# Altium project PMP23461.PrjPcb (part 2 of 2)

## Sheet PMP23461 CLLLC Sensing.SchDoc
size 431 x 279 mm; Date: Not shown in title block; ApprovedBy: Not shown in title block; CheckedBy: Not shown in title block; Author: Not shown in title block; CompanyName: Not shown in title block; Engineer: Not shown in title block; Organization: Not shown in title block; Address1: Not shown in title block; Address2: Not shown in title block; Address3: Not shown in title block; Address4: Not shown in title block; DocumentNumber: 2; Revision: Use project parameter SCH_Rev; SheetNumber: 2; SheetTotal: 2; PageSetup: Record=PageOptions¦CenterHorizontal=True¦CenterVertical=True¦PrintScale=1.00¦XCorrection=1.00¦YCorrection=1.00¦PrintKind=0¦BorderSize=5000000¦LeftOffset=0¦BottomOffset=0¦Orientation=2¦PaperLength=1000¦PaperWidth=1000¦Scale=100¦PaperSource=15¦PrintQuality=600¦MediaType=1¦DitherType=10¦PaperKind=Letter¦PrintScaleMode=1
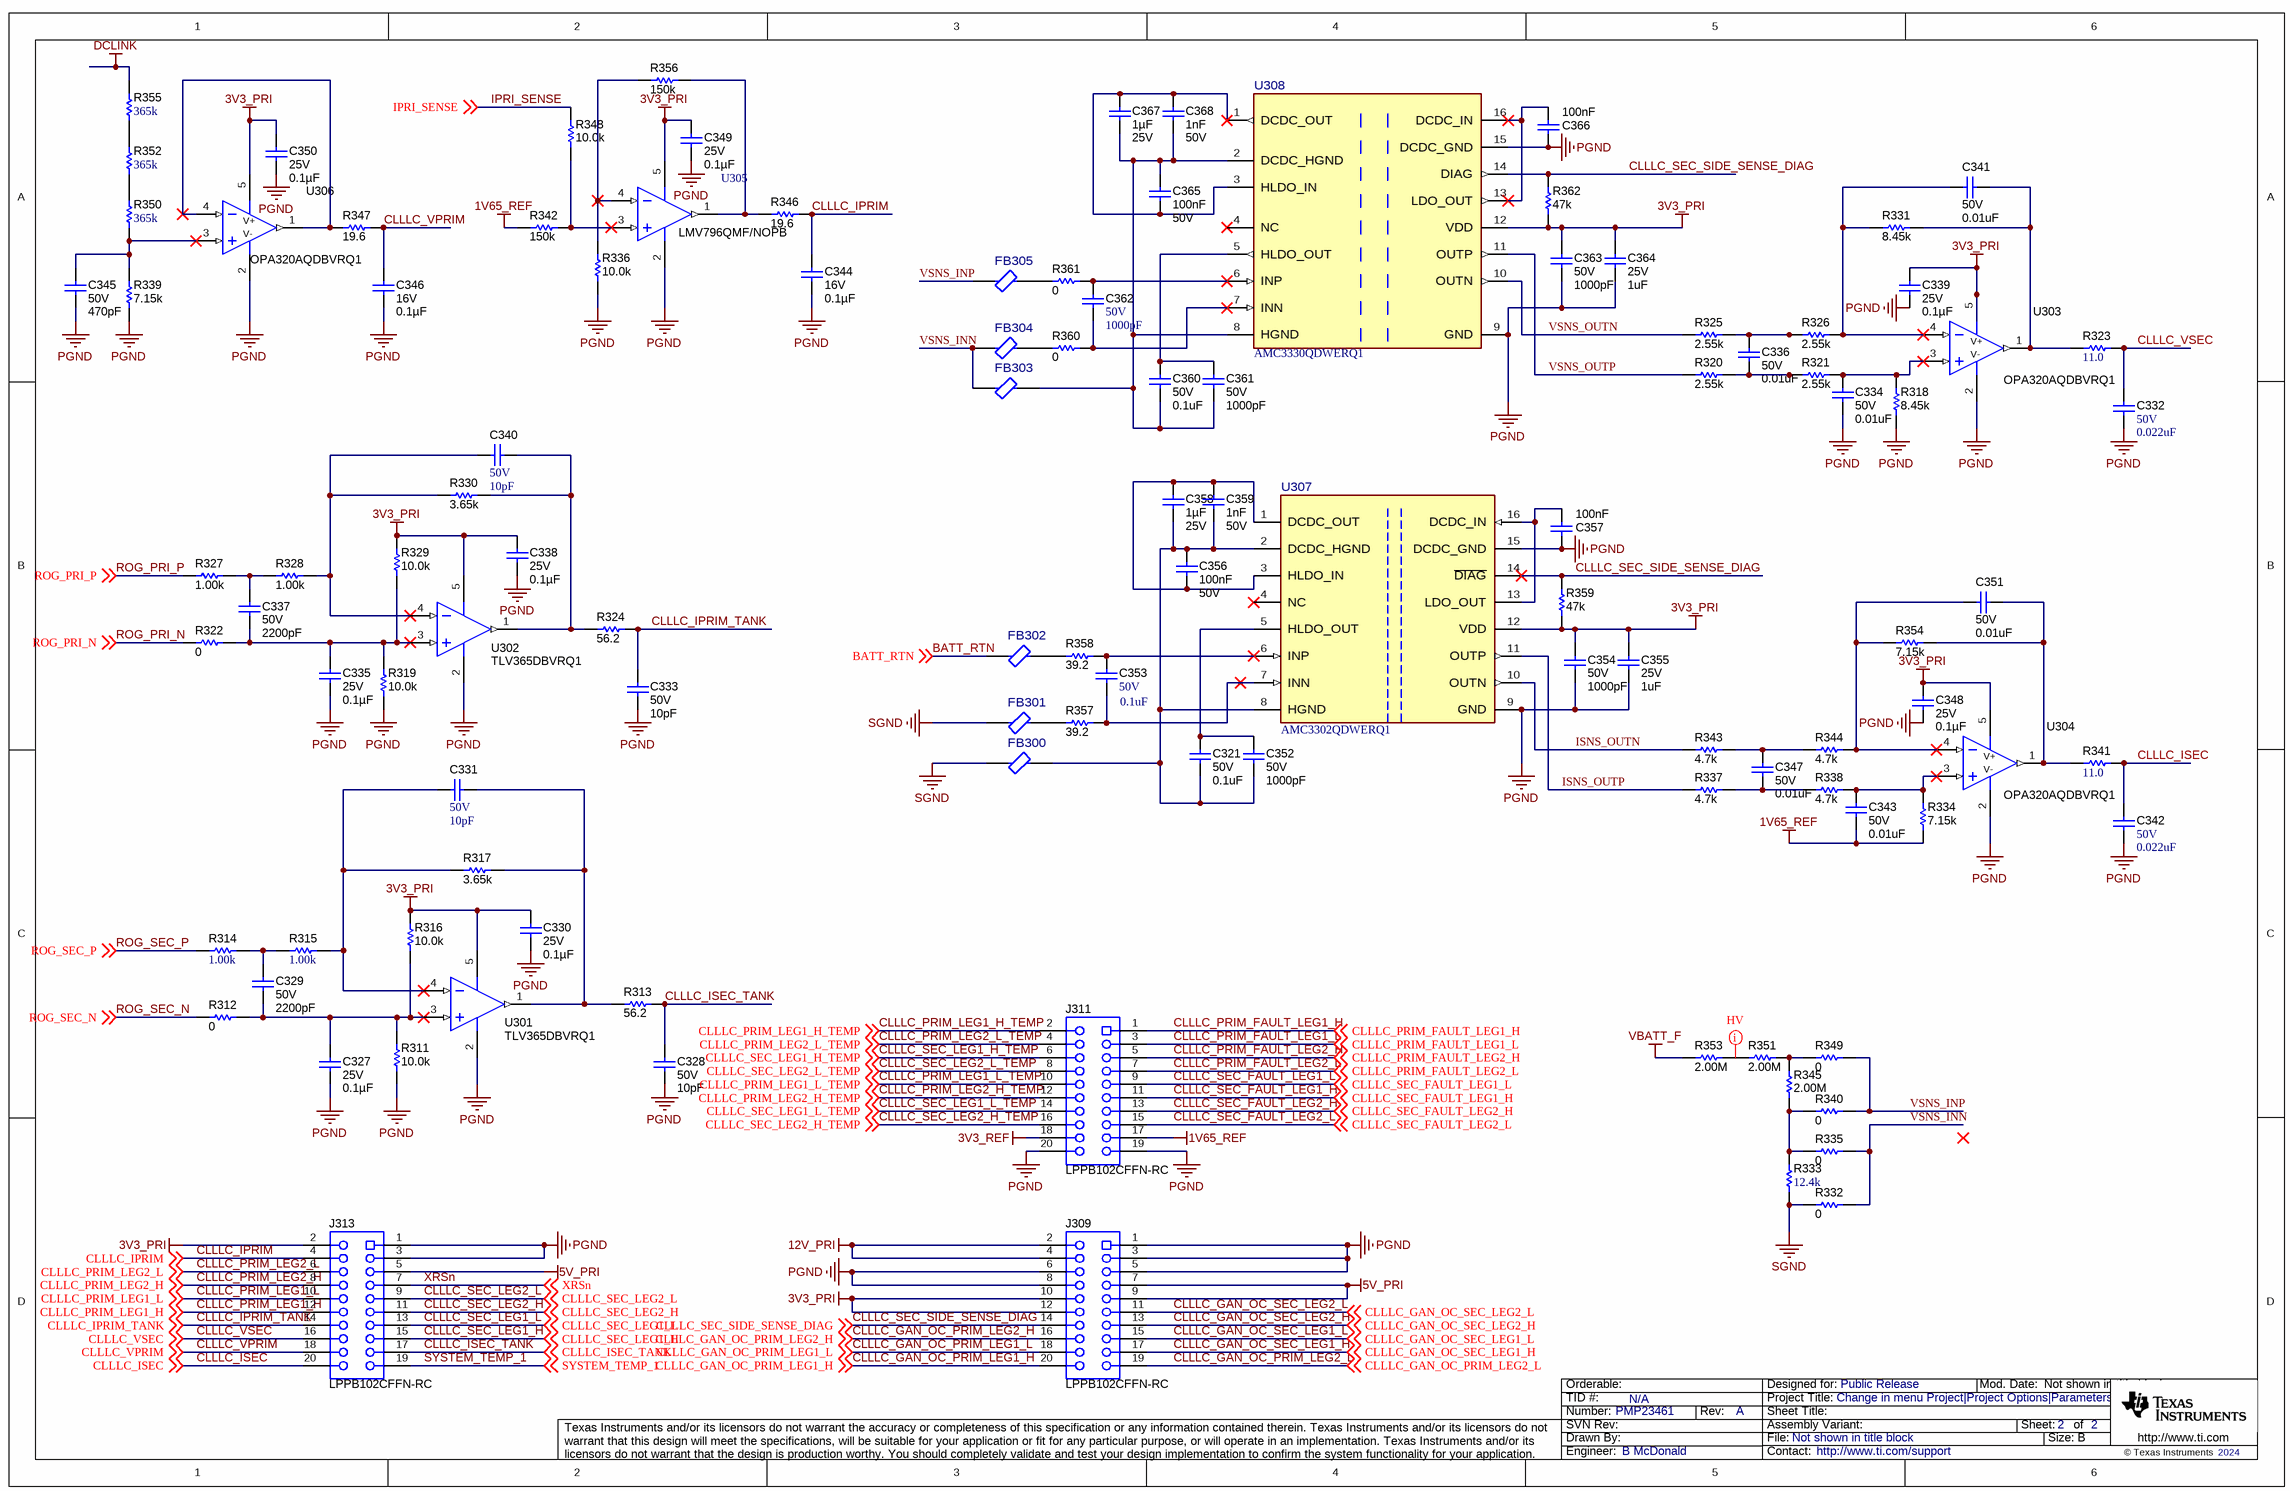
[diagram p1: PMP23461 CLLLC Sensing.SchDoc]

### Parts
C321  VDC_V: 50V  ValueDisplayed: 0.1uF  [1206_190]  (hidden comment: C3216NP01H104J160AA)
C327  VDC_V: 25V  ValueDisplayed: 0.1µF  [0402]  (hidden comment: CS0402KRX7R8BB104)
C328  VDC_V: 50V  ValueDisplayed: 10pF  [0402]  (hidden comment: 04025U100CAT2A)
C329  VDC_V: 50V  ValueDisplayed: 2200pF  [0402]  (hidden comment: C1005X7R1H222K050BE)
C330  VDC_V: 25V  ValueDisplayed: 0.1µF  [0402]  (hidden comment: CGA2B3X7R1E104K050BB)
C331  VDC_V: 50V  ValueDisplayed: 10pF  [0402]  (hidden comment: 04025U100CAT2A)
C332  VDC_V: 50V  ValueDisplayed: 0.022uF  [0402]  (hidden comment: CGA2B3X7R1H223K050BB)
C333  VDC_V: 50V  ValueDisplayed: 10pF  [0402]  (hidden comment: 04025U100CAT2A)
C334  VDC_V: 50V  ValueDisplayed: 0.01uF  [0402]  (hidden comment: CGA2B3X7R1H103K050BB)
C335  VDC_V: 25V  ValueDisplayed: 0.1µF  [0402]  (hidden comment: CGA2B3X7R1E104K050BB)
C336  VDC_V: 50V  ValueDisplayed: 0.01uF  [0402]  (hidden comment: CGA2B3X7R1H103K050BB)
C337  VDC_V: 50V  ValueDisplayed: 2200pF  [0402]  (hidden comment: CGA2B2X7R1H222K050BA)
C338  VDC_V: 25V  ValueDisplayed: 0.1µF  [0402]  (hidden comment: CGA2B3X7R1E104K050BB)
C339  VDC_V: 25V  ValueDisplayed: 0.1µF  [0402]  (hidden comment: CGA2B3X7R1E104K050BB)
C340  VDC_V: 50V  ValueDisplayed: 10pF  [0402]  (hidden comment: 04025U100CAT2A)
C341  VDC_V: 50V  ValueDisplayed: 0.01uF  [0402]  (hidden comment: CGA2B3X7R1H103K050BB)
C342  VDC_V: 50V  ValueDisplayed: 0.022uF  [0402]  (hidden comment: CGA2B3X7R1H223K050BB)
C343  VDC_V: 50V  ValueDisplayed: 0.01uF  [0402]  (hidden comment: CGA2B3X7R1H103K050BB)
C344  VDC_V: 16V  ValueDisplayed: 0.1µF  [0402]  (hidden comment: GCM155R71C104JA55D)
C345  VDC_V: 50V  ValueDisplayed: 470pF  [0402]  (hidden comment: GCM155R71H471KA37D)
C346  VDC_V: 16V  ValueDisplayed: 0.1µF  [0402]  (hidden comment: GCM155R71C104JA55D)
C347  VDC_V: 50V  ValueDisplayed: 0.01uF  [0402]  (hidden comment: CGA2B3X7R1H103K050BB)
C348  VDC_V: 25V  ValueDisplayed: 0.1µF  [0402]  (hidden comment: CGA2B3X7R1E104K050BB)
C349  VDC_V: 25V  ValueDisplayed: 0.1µF  [0402]  (hidden comment: CGA2B3X7R1E104K050BB)
C350  VDC_V: 25V  ValueDisplayed: 0.1µF  [0402]  (hidden comment: CGA2B3X7R1E104K050BB)
C351  VDC_V: 50V  ValueDisplayed: 0.01uF  [0402]  (hidden comment: CGA2B3X7R1H103K050BB)
C352  VDC_V: 50V  ValueDisplayed: 1000pF  [1206]  (hidden comment: 12065C102KAT2A)
C353  value 0.1uF  VDC_V: 50V  [0402]  (hidden comment: CGA2B3X7R1H104K050BB)
C354  VDC_V: 50V  ValueDisplayed: 1000pF  [1206]  (hidden comment: 12065C102KAT2A)
C355  VDC_V: 25V  ValueDisplayed: 1uF  [1206]  (hidden comment: 12063C105KAT2A)
C356  Cap_F: 100nF  VDC_V: 50V  [0603]  (hidden comment: C0603C104K5RACAUTO)
C357  Cap_F: 100nF  [0603]  (hidden comment: C0603C104K5RACAUTO)
C358  Cap_F: 1µF  VDC_V: 25V  [0603S]  (hidden comment: CGA3E1X7R1E105K080AC)
C359  Cap_F: 1nF  VDC_V: 50V  [0603]  (hidden comment: C0603C102K5RACTU)
C360  VDC_V: 50V  ValueDisplayed: 0.1uF  [1206_190]  (hidden comment: C3216NP01H104J160AA)
C361  VDC_V: 50V  ValueDisplayed: 1000pF  [1206]  (hidden comment: 12065C102KAT2A)
C362  VDC_V: 50V  ValueDisplayed: 1000pF  [0402]  (hidden comment: CGA2B2X7R1H102K050BA)
C363  VDC_V: 50V  ValueDisplayed: 1000pF  [1206]  (hidden comment: 12065C102KAT2A)
C364  VDC_V: 25V  ValueDisplayed: 1uF  [1206]  (hidden comment: 12063C105KAT2A)
C365  Cap_F: 100nF  VDC_V: 50V  [0603]  (hidden comment: C0603C104K5RACAUTO)
C366  Cap_F: 100nF  [0603]  (hidden comment: C0603C104K5RACAUTO)
C367  Cap_F: 1µF  VDC_V: 25V  [0603S]  (hidden comment: CGA3E1X7R1E105K080AC)
C368  Cap_F: 1nF  VDC_V: 50V  [0603]  (hidden comment: C0603C102K5RACTU)
FB300  MMZ1005Y182CTD25  [FP-MMZ1005Y182CTD25_0402-MFG]  (value not drawn)
FB301  MMZ1005Y182CTD25  [FP-MMZ1005Y182CTD25_0402-MFG]  (value not drawn)
FB302  MMZ1005Y182CTD25  [FP-MMZ1005Y182CTD25_0402-MFG]  (value not drawn)
FB303  MMZ1005Y182CTD25  [FP-MMZ1005Y182CTD25_0402-MFG]  (value not drawn)
FB304  MMZ1005Y182CTD25  [FP-MMZ1005Y182CTD25_0402-MFG]  (value not drawn)
FB305  MMZ1005Y182CTD25  [FP-MMZ1005Y182CTD25_0402-MFG]  (value not drawn)
J309  LPPB102CFFN-RC  [Sullins_LPPB102CFFN]
J311  LPPB102CFFN-RC  [Sullins_LPPB102CFFN]
J313  LPPB102CFFN-RC  [Sullins_LPPB102CFFN]
R311  ValueDisplayed: 10.0k  [0402]  (hidden comment: ERJPA2F1002X)
R312  ValueDisplayed: 0  [0402]  (hidden comment: CRCW04020000Z0ED)
R313  ValueDisplayed: 56.2  [0402]  (hidden comment: CRCW040256R2FKED)
R314  ValueDisplayed: 1.00k  [0402]  (hidden comment: CRCW04021K00FKED)
R315  ValueDisplayed: 1.00k  [0402]  (hidden comment: CRCW04021K00FKED)
R316  ValueDisplayed: 10.0k  [0402]  (hidden comment: ERJPA2F1002X)
R317  ValueDisplayed: 3.65k  [0402]  (hidden comment: CRCW04023K65FKED)
R318  ValueDisplayed: 8.45k  [0402]  (hidden comment: CRCW04028K45FKED)
R319  ValueDisplayed: 10.0k  [0402]  (hidden comment: ERJPA2F1002X)
R320  ValueDisplayed: 2.55k  [0402]  (hidden comment: CRCW04022K55FKED)
R321  ValueDisplayed: 2.55k  [0402]  (hidden comment: CRCW04022K55FKED)
R322  ValueDisplayed: 0  [0402]  (hidden comment: CRCW04020000Z0ED)
R323  ValueDisplayed: 11.0  [0402]  (hidden comment: CRCW040211R0FKED)
R324  ValueDisplayed: 56.2  [0402]  (hidden comment: CRCW040256R2FKED)
R325  ValueDisplayed: 2.55k  [0402]  (hidden comment: CRCW04022K55FKED)
R326  ValueDisplayed: 2.55k  [0402]  (hidden comment: CRCW04022K55FKED)
R327  ValueDisplayed: 1.00k  [0402]  (hidden comment: CRCW04021K00FKED)
R328  ValueDisplayed: 1.00k  [0402]  (hidden comment: CRCW04021K00FKED)
R329  ValueDisplayed: 10.0k  [0402]  (hidden comment: ERJPA2F1002X)
R330  ValueDisplayed: 3.65k  [0402]  (hidden comment: CRCW04023K65FKED)
R331  ValueDisplayed: 8.45k  [0402]  (hidden comment: CRCW04028K45FKED)
R332  ValueDisplayed: 0  [0402]  (hidden comment: CRCW04020000Z0ED)
R333  ValueDisplayed: 12.4k  [1206]  (hidden comment: ERJ-8ENF1242V)
R334  ValueDisplayed: 7.15k  [0402]  (hidden comment: CRCW04027K15FKED)
R335  ValueDisplayed: 0  [0402]  (hidden comment: CRCW04020000Z0ED)
R336  ValueDisplayed: 10.0k  [0402]  (hidden comment: ERJPA2F1002X)
R337  ValueDisplayed: 4.7k  [0402]  (hidden comment: CRCW04024K70JNED)
R338  ValueDisplayed: 4.7k  [0402]  (hidden comment: CRCW04024K70JNED)
R339  ValueDisplayed: 7.15k  [0603]  (hidden comment: CRCW06037K15FKEA)
R340  ValueDisplayed: 0  [0402]  (hidden comment: CRCW04020000Z0ED)
R341  ValueDisplayed: 11.0  [0402]  (hidden comment: CRCW040211R0FKED)
R342  ValueDisplayed: 150k  [0402]  (hidden comment: CRCW0402150KFKED)
R343  ValueDisplayed: 4.7k  [0402]  (hidden comment: CRCW04024K70JNED)
R344  ValueDisplayed: 4.7k  [0402]  (hidden comment: CRCW04024K70JNED)
R345  ValueDisplayed: 2.00M  [1206]  (hidden comment: CRCW12062M00FKEA)
R346  ValueDisplayed: 19.6  [0402]  (hidden comment: CRCW040219R6FKED)
R347  ValueDisplayed: 19.6  [0402]  (hidden comment: CRCW040219R6FKED)
R348  ValueDisplayed: 10.0k  [0402]  (hidden comment: ERJPA2F1002X)
R349  ValueDisplayed: 0  [0402]  (hidden comment: CRCW04020000Z0ED)
R350  ValueDisplayed: 365k  [1206]  (hidden comment: CRCW1206365KFKEA)
R351  ValueDisplayed: 2.00M  [1206]  (hidden comment: CRCW12062M00FKEA)
R352  ValueDisplayed: 365k  [1206]  (hidden comment: CRCW1206365KFKEA)
R353  ValueDisplayed: 2.00M  [1206]  (hidden comment: CRCW12062M00FKEA)
R354  ValueDisplayed: 7.15k  [0402]  (hidden comment: CRCW04027K15FKED)
R355  ValueDisplayed: 365k  [1206]  (hidden comment: CRCW1206365KFKEA)
R356  ValueDisplayed: 150k  [0402]  (hidden comment: CRCW0402150KFKED)
R357  ValueDisplayed: 39.2  [0402]  (hidden comment: CRCW040239R2FKED)
R358  ValueDisplayed: 39.2  [0402]  (hidden comment: CRCW040239R2FKED)
R359  ValueDisplayed: 47k  [0603]  (hidden comment: CRCW060347K0JNEA)
R360  ValueDisplayed: 0  [0402]  (hidden comment: CRCW04020000Z0ED)
R361  ValueDisplayed: 0  [0402]  (hidden comment: CRCW04020000Z0ED)
R362  ValueDisplayed: 47k  [0603]  (hidden comment: CRCW060347K0JNEA)
U301  TLV365DBVRQ1  [DBV0005A-MFG]
U302  TLV365DBVRQ1  [DBV0005A-MFG]
U303  OPA320AQDBVRQ1  [DBV0005A_N]
U304  OPA320AQDBVRQ1  [DBV0005A_N]
U305  LMV796QMF/NOPB  [DBV0005A_N]
U306  OPA320AQDBVRQ1  [DBV0005A_N]
U307  AMC3302QDWERQ1  [DWE0016A-MFG]
U308  AMC3330QDWERQ1  [DWE0016A-MFG]

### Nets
1V65_REF: C343.1 J311.17 R334.1 R342.1
3V3_PRI: C330.1 C338.1 C339.1 C348.1 C349.1 C350.1 C354.1 C355.1 C363.1 C364.1 J309.10 J309.12 J313.2 R316.2 R329.2 R359.1 R362.1 U301.5(V+) U302.5(V+) U303.5(V+) U304.5(V+) U305.5(V+) U306.5(V+) U307.12(VDD) U308.12(VDD)
3V3_REF: J311.18
5V_PRI: J309.7 J309.9 J313.5
12V_PRI: J309.2 J309.4
DCLINK: R355.1
PGND: C327.2 C328.2 C330.2 C332.2 C333.2 C334.1 C335.2 C338.2 C339.2 C342.2 C344.2 C345.2 C346.2 C348.2 C349.2 C350.2 C354.2 C355.2 C357.2 C363.2 C364.2 C366.2 J309.1 J309.3 J309.5 J309.6 J309.8 J311.19 J311.20 J313.1 J313.3 R311.1 R318.1 R319.1 R336.1 R339.2 U301.2(V-) U302.2(V-) U303.2(V-) U304.2(V-) U305.2(V-) U306.2(V-) U307.9(GND) U307.15(DCDC_GND) U308.9(GND) U308.15(DCDC_GND)
SGND: FB300.1 FB301.1 R332.1 R333.2
VBATT_F: R353.2
BATT_RTN: FB302.1 ; off-sheet BATT_RTN
CLLLC_GAN_OC_PRIM_LEG1_H: J309.20 ; off-sheet CLLLC_GAN_OC_PRIM_LEG1_H
CLLLC_GAN_OC_PRIM_LEG1_L: J309.18 ; off-sheet CLLLC_GAN_OC_PRIM_LEG1_L
CLLLC_GAN_OC_PRIM_LEG2_H: J309.16 ; off-sheet CLLLC_GAN_OC_PRIM_LEG2_H
CLLLC_GAN_OC_PRIM_LEG2_L: J309.19 ; off-sheet CLLLC_GAN_OC_PRIM_LEG2_L
CLLLC_GAN_OC_SEC_LEG1_H: J309.17 ; off-sheet CLLLC_GAN_OC_SEC_LEG1_H
CLLLC_GAN_OC_SEC_LEG1_L: J309.15 ; off-sheet CLLLC_GAN_OC_SEC_LEG1_L
CLLLC_GAN_OC_SEC_LEG2_H: J309.13 ; off-sheet CLLLC_GAN_OC_SEC_LEG2_H
CLLLC_GAN_OC_SEC_LEG2_L: J309.11 ; off-sheet CLLLC_GAN_OC_SEC_LEG2_L
CLLLC_IPRIM: C344.1 J313.4 R346.2 ; off-sheet CLLLC_IPRIM
CLLLC_IPRIM_TANK: C333.1 J313.14 R324.2 ; off-sheet CLLLC_IPRIM_TANK
CLLLC_ISEC: C342.1 J313.20 R341.2 ; off-sheet CLLLC_ISEC
CLLLC_ISEC_TANK: C328.1 J313.17 R313.2 ; off-sheet CLLLC_ISEC_TANK
CLLLC_PRIM_FAULT_LEG1_H: J311.1 ; off-sheet CLLLC_PRIM_FAULT_LEG1_H
CLLLC_PRIM_FAULT_LEG1_L: J311.3 ; off-sheet CLLLC_PRIM_FAULT_LEG1_L
CLLLC_PRIM_FAULT_LEG2_H: J311.5 ; off-sheet CLLLC_PRIM_FAULT_LEG2_H
CLLLC_PRIM_FAULT_LEG2_L: J311.7 ; off-sheet CLLLC_PRIM_FAULT_LEG2_L
CLLLC_PRIM_LEG1_H: J313.12 ; off-sheet CLLLC_PRIM_LEG1_H
CLLLC_PRIM_LEG1_H_TEMP: J311.2 ; off-sheet CLLLC_PRIM_LEG1_H_TEMP
CLLLC_PRIM_LEG1_L: J313.10 ; off-sheet CLLLC_PRIM_LEG1_L
CLLLC_PRIM_LEG1_L_TEMP: J311.10 ; off-sheet CLLLC_PRIM_LEG1_L_TEMP
CLLLC_PRIM_LEG2_H: J313.8 ; off-sheet CLLLC_PRIM_LEG2_H
CLLLC_PRIM_LEG2_H_TEMP: J311.12 ; off-sheet CLLLC_PRIM_LEG2_H_TEMP
CLLLC_PRIM_LEG2_L: J313.6 ; off-sheet CLLLC_PRIM_LEG2_L
CLLLC_PRIM_LEG2_L_TEMP: J311.4 ; off-sheet CLLLC_PRIM_LEG2_L_TEMP
CLLLC_SEC_FAULT_LEG1_H: J311.11 ; off-sheet CLLLC_SEC_FAULT_LEG1_H
CLLLC_SEC_FAULT_LEG1_L: J311.9 ; off-sheet CLLLC_SEC_FAULT_LEG1_L
CLLLC_SEC_FAULT_LEG2_H: J311.13 ; off-sheet CLLLC_SEC_FAULT_LEG2_H
CLLLC_SEC_FAULT_LEG2_L: J311.15 ; off-sheet CLLLC_SEC_FAULT_LEG2_L
CLLLC_SEC_LEG1_H: J313.15 ; off-sheet CLLLC_SEC_LEG1_H
CLLLC_SEC_LEG1_H_TEMP: J311.6 ; off-sheet CLLLC_SEC_LEG1_H_TEMP
CLLLC_SEC_LEG1_L: J313.13 ; off-sheet CLLLC_SEC_LEG1_L
CLLLC_SEC_LEG1_L_TEMP: J311.14 ; off-sheet CLLLC_SEC_LEG1_L_TEMP
CLLLC_SEC_LEG2_H: J313.11 ; off-sheet CLLLC_SEC_LEG2_H
CLLLC_SEC_LEG2_H_TEMP: J311.16 ; off-sheet CLLLC_SEC_LEG2_H_TEMP
CLLLC_SEC_LEG2_L: J313.9 ; off-sheet CLLLC_SEC_LEG2_L
CLLLC_SEC_LEG2_L_TEMP: J311.8 ; off-sheet CLLLC_SEC_LEG2_L_TEMP
CLLLC_SEC_SIDE_SENSE_DIAG: J309.14 R359.2 R362.2 U307.14(~{DIAG}) U308.14(DIAG) ; off-sheet CLLLC_SEC_SIDE_SENSE_DIAG
CLLLC_VPRIM: C346.1 J313.18 R347.2 ; off-sheet CLLLC_VPRIM
CLLLC_VSEC: C332.1 J313.16 R323.2 ; off-sheet CLLLC_VSEC
IPRI_SENSE: R348.2 ; off-sheet IPRI_SENSE
ISNS_OUTN: R343.1 U307.10(OUTN)
ISNS_OUTP: R337.1 U307.11(OUTP)
ROG_PRI_N: R322.1 ; off-sheet ROG_PRI_N
ROG_PRI_P: R327.1 ; off-sheet ROG_PRI_P
ROG_SEC_N: R312.1 ; off-sheet ROG_SEC_N
ROG_SEC_P: R314.1 ; off-sheet ROG_SEC_P
SYSTEM_TEMP_1: J313.19 ; off-sheet SYSTEM_TEMP_1
VSNS_INN: FB303.1 FB304.1 R332.2 R335.2
VSNS_INP: FB305.1 R340.2 R349.2
VSNS_OUTN: R325.1 U308.10(OUTN)
VSNS_OUTP: R320.1 U308.11(OUTP)
XRSn: J313.7 ; off-sheet XRSn
NetC321_1: C321.1 C352.1 U307.5(HLDO_OUT)
NetC321_2: C321.2 C352.2 C356.1 C358.2 C359.2 FB300.2 U307.2(DCDC_HGND) U307.8(HGND)
NetC327_1: C327.1 C329.1 R311.2 R312.2 R316.1 U301.3(+IN)
NetC329_2: C329.2 R314.2 R315.1
NetC331_1: C331.1 R313.1 R317.2 U301.1(VOUT)
NetC331_2: C331.2 R315.2 R317.1 U301.4(-IN)
NetC334_2: C334.2 R318.2 R321.2 U303.3(IN+)
NetC335_1: C335.1 C337.1 R319.2 R322.2 R329.1 U302.3(+IN)
NetC336_1: C336.1 R320.2 R321.1
NetC336_2: C336.2 R325.2 R326.1
NetC337_2: C337.2 R327.2 R328.1
NetC340_1: C340.1 R324.1 R330.2 U302.1(VOUT)
NetC340_2: C340.2 R328.2 R330.1 U302.4(-IN)
NetC341_1: C341.1 R323.1 R331.1 U303.1(OUT)
NetC341_2: C341.2 R326.2 R331.2 U303.4(IN-)
NetC343_2: C343.2 R334.2 R338.2 U304.3(IN+)
NetC345_1: C345.1 R339.1 R350.2 U306.3(IN+)
NetC347_1: C347.1 R337.2 R338.1
NetC347_2: C347.2 R343.2 R344.1
NetC351_1: C351.1 R341.1 R354.2 U304.1(OUT)
NetC351_2: C351.2 R344.2 R354.1 U304.4(IN-)
NetC353_1: C353.1 R357.2 U307.7(INN)
NetC353_2: C353.2 R358.2 U307.6(INP)
NetC356_2: C356.2 C358.1 C359.1 U307.1(DCDC_OUT) U307.3(HLDO_IN)
NetC357_1: C357.1 U307.13(LDO_OUT) U307.16(DCDC_IN)
NetC360_1: C360.1 C361.1 U308.5(HLDO_OUT)
NetC360_2: C360.2 C361.2 C365.1 C367.2 C368.2 FB303.2 U308.2(DCDC_HGND) U308.8(HGND)
NetC362_1: C362.1 R360.2 U308.7(INN)
NetC362_2: C362.2 R361.2 U308.6(INP)
NetC365_2: C365.2 C367.1 C368.1 U308.1(DCDC_OUT) U308.3(HLDO_IN)
NetC366_1: C366.1 U308.13(LDO_OUT) U308.16(DCDC_IN)
NetFB301_2: FB301.2 R357.1
NetFB302_2: FB302.2 R358.1
NetFB304_2: FB304.2 R360.1
NetFB305_2: FB305.2 R361.1
NetR333_1: R333.1 R335.1 R340.1 R345.1
NetR336_2: R336.2 R356.1 U305.4(IN-)
NetR342_2: R342.2 R348.1 U305.3(IN+)
NetR345_2: R345.2 R349.1 R351.1
NetR346_1: R346.1 R356.2 U305.1(OUT)
NetR347_1: R347.1 U306.1(OUT) U306.4(IN-)
NetR350_1: R350.1 R352.2
NetR351_2: R351.2 R353.1
NetR352_1: R352.1 R355.2

Not connected (* = marked no-connect by the designer): U307 4(NC)*; U308 4(NC)*

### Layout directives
mark named HV: NetR351_2

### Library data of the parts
C321 C360 = CMP-0008647-2: CAP, CERM, 0.1 uF, 50 V, +/- 5%, C0G/NP0, 1206_190; Manufacturer: TDK; TaMin_C: -55°C; Polarized: N; SizeAreaWB_mm2: 10.92; Value1: Unknown; U/M: EA; Value: 0.1uF; TaMax_C: 150°C; SizeZ_mm: 1.9; SizeX_mm: 3.2; SizeY_mm: 1.6; Cap_Case: 1206; SizeArea_mm2: 5.12; Cap_F: 100nF; AEC Category: Q200
C327 = CMP-0080610-1: CAP, CERM, 0.1 µF, 25 V,+/- 10%, X7R, AEC-Q200 Grade 1, 0402; Manufacturer: TDK; PartNumber: CGA2B3X7R1E104K050BB; TaMin_C: -55°C; Polarized: N; SizeAreaWB_mm2: 3; U/M: EA; Value: 0.1uF; TaMax_C: 125°C; SizeZ_mm: 0.6; SizeX_mm: 1; SizeY_mm: 0.5; AEC Qualified: Y; Cap_F: 100nF; AEC Category: Q200
C328 C331 C333 C340 = CMP-0064911-2: CAP, CERM, 10 pF, 50 V,+/- 2.5%, C0G/NP0, AEC-Q200 Grade 1, 0402; Manufacturer: AVX; TaMin_C: -55°C; Polarized: N; SizeAreaWB_mm2: 3; Value1: Unknown; U/M: EA; Value: 10pF; TaMax_C: 125°C; SizeZ_mm: 0.6; SizeX_mm: 1; SizeY_mm: 0.5; AEC Qualified: Y; AEC Category: Q200
C329 = CMP-0006317-2: CAP, CERM, 2200 pF, 50 V, +/- 10%, X7R, AEC-Q200 Grade 1, 0402; Manufacturer: TDK; PartNumber: CGA2B2X7R1H222K050BA; TaMin_C: -55°C; ESR_ohm: 1.07794; Polarized: N; SizeAreaWB_mm2: 3; Value1: 1.07794 ohm; U/M: EA; Value: 2200pF; TaMax_C: 125°C; SizeZ_mm: 0.6; SizeX_mm: 1; SizeY_mm: 0.5; AEC Qualified: Y; Cap_F: 2.2nF; IRMS_A: 264.071mA; AEC Category: Q200
C330 C335 C338 C339 C348-C350 = CMP-0080610-1: CAP, CERM, 0.1 µF, 25 V,+/- 10%, X7R, AEC-Q200 Grade 1, 0402; Manufacturer: TDK; TaMin_C: -55°C; Polarized: N; SizeAreaWB_mm2: 3; U/M: EA; Value: 0.1uF; TaMax_C: 125°C; SizeZ_mm: 0.6; SizeX_mm: 1; SizeY_mm: 0.5; AEC Qualified: Y; Cap_F: 100nF; AEC Category: Q200
C332 C342 = CMP-0006328-2: CAP, CERM, 0.022 uF, 50 V, +/- 10%, X7R, AEC-Q200 Grade 1, 0402; Manufacturer: TDK; TaMin_C: -55°C; Polarized: N; SizeAreaWB_mm2: 3; Value1: 0.141987 ohm; U/M: EA; TaMax_C: 125°C; SizeZ_mm: 0.6; SizeX_mm: 1; SizeY_mm: 0.5; AEC Qualified: Y; Cap_F: 22nF; AEC Category: Q200; ESR_ohm: 0.142; IRMS_A: 451.393mA
C334 C336 C341 C343 C347 C351 = CMP-0006324-2: CAP, CERM, 0.01 uF, 50 V, +/- 10%, X7R, AEC-Q200 Grade 1, 0402; Manufacturer: TDK; TaMin_C: -55°C; ESR_ohm: 0.333065; Polarized: N; SizeAreaWB_mm2: 3; Value1: 0.333065 ohm; U/M: EA; Value: 0.01uF; TaMax_C: 125°C; SizeZ_mm: 0.6; SizeX_mm: 1; SizeY_mm: 0.5; AEC Qualified: Y; Cap_F: 10nF; IRMS_A: 323.373mA; AEC Category: Q200
C337 = CMP-0006317-2: CAP, CERM, 2200 pF, 50 V, +/- 10%, X7R, AEC-Q200 Grade 1, 0402; Manufacturer: TDK; TaMin_C: -55°C; ESR_ohm: 1.07794; Polarized: N; SizeAreaWB_mm2: 3; Value1: 1.07794 ohm; U/M: EA; Value: 2200pF; TaMax_C: 125°C; SizeZ_mm: 0.6; SizeX_mm: 1; SizeY_mm: 0.5; AEC Qualified: Y; Cap_F: 2.2nF; IRMS_A: 264.071mA; AEC Category: Q200
C344 C346 = CMP-0080702-1: CAP, CERM, 0.1 µF, 16 V,+/- 5%, X7R, AEC-Q200 Grade 1, 0402; Manufacturer: MuRata; Cap_F: 100nF; SizeAreaWB_mm2: 3; SizeArea_mm2: 0.5; AEC Qualified: Y; AEC Category: Q200; Value: 0.1uF; TaMax_C: 125°C; SizeZ_mm: 0.6; AEC Grade: 1; Polarized: N; TaMin_C: -55°C; U/M: EA
C345 = CMP-0006360-2: CAP, CERM, 470 pF, 50 V, +/- 10%, X7R, AEC-Q200 Grade 1, 0402; Manufacturer: MuRata; TaMin_C: -55°C; Polarized: N; SizeAreaWB_mm2: 3; Value1: Unknown; U/M: EA; Value: 470pF; TaMax_C: 125°C; SizeZ_mm: 0.6; SizeX_mm: 1; SizeY_mm: 0.5; AEC Qualified: Y; AEC Category: Q200
C352 C354 C361 C363 = CMP-0008530-2: CAP, CERM, 1000 pF, 50 V, +/- 10%, X7R, 1206; Manufacturer: AVX; TaMin_C: -55°C; ESR_ohm: 0.427; Polarized: N; SizeAreaWB_mm2: 10.92; Value1: 0.427 ohm; U/M: EA; Value: 1000pF; TaMax_C: 125°C; SizeZ_mm: 1.35; SizeY_mm: 1.6; SizeArea_mm2: 5.12; Cap_F: 1nF; SizeX_mm: 3.2; AEC Category: Q200
C353 = CMP-0006325-2: CAP, CERM, 0.1 uF, 50 V, +/- 10%, X7R, AEC-Q200 Grade 1, 0402; Manufacturer: TDK; TaMin_C: -55°C; ESR_ohm: 39.064m; Polarized: N; SizeAreaWB_mm2: 3; Value1: 0.039064 ohm; U/M: EA; TaMax_C: 125°C; SizeZ_mm: 0.6; SizeX_mm: 1; SizeY_mm: 0.5; AEC Qualified: Y; Cap_F: 100nF; IRMS_A: 814.669mA; AEC Category: Q200
C355 C364 = CMP-0008509-2: CAP, CERM, 1 uF, 25 V, +/- 10%, X7R, 1206; Manufacturer: AVX; TaMin_C: -55°C; ESR_ohm: 13m; Polarized: N; SizeAreaWB_mm2: 10.92; Value1: 0.013 ohm; U/M: EA; Value: 1uF; TaMax_C: 125°C; SizeZ_mm: 1.35; SizeX_mm: 3.2; SizeY_mm: 1.6; SizeArea_mm2: 5.12; Cap_F: 1µF; AEC Category: Q200
C356 C365 = CMP-0079602-1: CAP, CERM, 0.1 µF, 50 V,+/- 10%, X7R, AEC-Q200 Grade 1, 0603; Manufacturer: Kemet; TaMin_C: -55°C; Polarized: N; SizeAreaWB_mm2: 4.68; U/M: EA; Value: 0.1uF; TaMax_C: 125°C; SizeZ_mm: 1; SizeX_mm: 1.6; SizeY_mm: 0.8; SizeArea_mm2: 1.28; AEC Qualified: Y; AEC Category: Q200; ValueDisplayed: 0.1µF
C357 C366 = CMP-0079602-1: CAP, CERM, 0.1 µF, 50 V,+/- 10%, X7R, AEC-Q200 Grade 1, 0603; Manufacturer: Kemet; TaMin_C: -55°C; Polarized: N; SizeAreaWB_mm2: 4.68; U/M: EA; Value: 0.1uF; TaMax_C: 125°C; SizeZ_mm: 1; SizeX_mm: 1.6; SizeY_mm: 0.8; Value2: 50V; SizeArea_mm2: 1.28; AEC Qualified: Y; AEC Category: Q200; ValueDisplayed: 0.1µF
C358 C367 = CMP-0076705-3: CAP, CERM, 1 µF, 25 V,+/- 10%, X7R, AEC-Q200 Grade 1, 0603; Manufacturer: TDK; SizeAreaWB_mm2: 4.68; SizeArea_mm2: 1.28; AEC Qualified: Y; AEC Category: Q200; Value: 1uF; TaMax_C: 125°C; SizeZ_mm: 1.0; AEC Grade: 1; Polarized: N; TaMin_C: -55°C; SizeY_mm: 0.8; U/M: EA; SizeX_mm: 1.6; Cap_Case: 1.6x0.8x0.8mm
C359 C368 = CMP-0006847-4: CAP, CERM, 1000 pF, 50 V, +/- 10%, X7R, 0603; Manufacturer: Kemet; TaMin_C: -55°C; Polarized: N; SizeAreaWB_mm2: 4.68; Value1: Unknown; U/M: EA; Value: 1000pF; TaMax_C: 125°C; SizeZ_mm: 1; SizeX_mm: 1.6; SizeY_mm: 0.8; SizeArea_mm2: 1.28; AEC Category: Q200
C362 = CMP-0006314-2: CAP, CERM, 1000 pF, 50 V, +/- 10%, X7R, AEC-Q200 Grade 1, 0402; Manufacturer: TDK; TaMin_C: -55°C; ESR_ohm: 2.2556; Polarized: N; SizeAreaWB_mm2: 3; Value1: 2.25564 ohm; U/M: EA; Value: 1000pF; TaMax_C: 125°C; SizeZ_mm: 0.6; SizeX_mm: 1; SizeY_mm: 0.5; AEC Qualified: Y; Cap_F: 1nF; IRMS_A: 280.466mA; AEC Category: Q200
FB300-FB305 = CMP-0090600-1: 1.8 kOhms @ 100MHz 1 Signal Line Ferrite Bead 0402 (1005 Metric) 150mA 850mOhm; Manufacturer: TDK; DCR_ohm: 0.85; Impedance At Frequency: 1800Ω @ 100MHz; AEC Qualified: Yes; Tolerance_%: 25%; SizeZ_mm: 0.55mm; AEC Grade: Grade 1
J309 J311 J313 = CMP-0750171-1: Receptacle, 1.27mm, 10x2, Gold, TH; Manufacturer: Sullins Connector Solutions; Gender: Female; Current_A: 1A; Cert_UL: Y; Row_Count: 2; Pitch_mm: 1.27
R311 R316 R319 R329 R336 R348 = CMP-0078779-1: RES, 10.0 k, 1%, 0.2 W, AEC-Q200 Grade 0, 0402; Manufacturer: Panasonic; Value_Code: 10k0; SizeArea_mm2: 0.5; AEC Qualified: Y; AEC Category: Q200; Res_ohm: 10k; Value: 10.0k; SizeZ_mm: 0.6; EIA_Code: E96; TempCo: 100 ppm/C; AEC Grade: 0; Power_W: 200mW; VDC_V: 50V; Value2: 0.2W; SizeX_mm: 1
R312 R322 R332 R335 R340 R349 R360 R361 = CMP-0026822-3: RES, 0, 5%, 0.063 W, AEC-Q200 Grade 0, 0402; Manufacturer: Vishay-Dale; Power_W: 63mW; TempCo: 200 ppm/C; Value_Code: 0000; Value: 0; EIA_Code: E24; SizeX_mm: 1; SizeY_mm: 0.5; SizeZ_mm: 0.6; Value2: 0.063W; AEC Qualified: Y; VDC_V: 50V; AEC Category: Q200
R313 R324 = CMP-0026454-2: RES, 56.2, 1%, 0.063 W, AEC-Q200 Grade 0, 0402; Manufacturer: Vishay-Dale; Power_W: 63mW; TempCo: 100 ppm/C; Value_Code: 56R2; Value: 56.2; EIA_Code: E96; SizeX_mm: 1; SizeY_mm: 0.5; SizeZ_mm: 0.6; Value2: 0.063W; AEC Qualified: Y; VDC_V: 50V; AEC Category: Q200; AEC Grade: 0
R314 R315 R327 R328 = CMP-0026071-3: RES, 1.00 k, 1%, 0.063 W, AEC-Q200 Grade 0, 0402; Manufacturer: Vishay-Dale; Power_W: 63mW; TempCo: 100 ppm/C; Value_Code: 1k00; Value: 1.00k; EIA_Code: E96; Res_ohm: 1k; SizeX_mm: 1; SizeY_mm: 0.5; SizeZ_mm: 0.6; Value2: 0.063W; AEC Qualified: Y; VDC_V: 50V; AEC Category: Q200; AEC Grade: 0
R317 R330 = CMP-0026337-2: RES, 3.65 k, 1%, 0.063 W, AEC-Q200 Grade 0, 0402; Manufacturer: Vishay-Dale; Power_W: 63mW; TempCo: 100 ppm/C; Value_Code: 3k65; Value: 3.65k; EIA_Code: E96; SizeX_mm: 1; SizeY_mm: 0.5; SizeZ_mm: 0.6; Value2: 0.063W; AEC Qualified: Y; VDC_V: 50V; AEC Category: Q200; AEC Grade: 0
R318 R331 = CMP-0026590-2: RES, 8.45 k, 1%, 0.063 W, AEC-Q200 Grade 0, 0402; Manufacturer: Vishay-Dale; Power_W: 63mW; TempCo: 100 ppm/C; Value_Code: 8k45; Value: 8.45k; EIA_Code: E96; SizeX_mm: 1; SizeY_mm: 0.5; SizeZ_mm: 0.6; Value2: 0.063W; AEC Qualified: Y; VDC_V: 50V; AEC Category: Q200; AEC Grade: 0
R320 R321 R325 R326 = CMP-0026238-2: RES, 2.55 k, 1%, 0.063 W, AEC-Q200 Grade 0, 0402; Manufacturer: Vishay-Dale; Power_W: 63mW; TempCo: 100 ppm/C; Value_Code: 2k55; Value: 2.55k; EIA_Code: E96; SizeX_mm: 1; SizeY_mm: 0.5; SizeZ_mm: 0.6; Value2: 0.063W; AEC Qualified: Y; VDC_V: 50V; AEC Category: Q200; AEC Grade: 0
R323 R341 = CMP-0025979-3: RES, 11.0, 1%, 0.063 W, AEC-Q200 Grade 0, 0402; Manufacturer: Vishay-Dale; Power_W: 63mW; TempCo: 100 ppm/C; Value_Code: 11R0; Value: 11.0; EIA_Code: E96; Res_ohm: 11; SizeX_mm: 1; SizeY_mm: 0.5; SizeZ_mm: 0.6; Value2: 0.063W; AEC Qualified: Y; VDC_V: 50V; AEC Category: Q200; AEC Grade: 0
R333 = CMP-0017331-3: RES, 12.4 k, 1%, 0.25 W, AEC-Q200 Grade 0, 1206; Manufacturer: Panasonic; Power_W: 250mW; TempCo: 100 ppm/C; Value_Code: 12k4; Value: 12.4k; EIA_Code: E96; SizeX_mm: 3.2; SizeY_mm: 1.6; SizeZ_mm: 1.35; Value2: 0.25W; SizeArea_mm2: 5.12; AEC Qualified: Y; VDC_V: 200V; AEC Category: Q200; AEC Grade: 0; SizeAreaWB_mm2: 10.92
R334 R354 = CMP-0026553-2: RES, 7.15 k, 1%, 0.063 W, AEC-Q200 Grade 0, 0402; Manufacturer: Vishay-Dale; Power_W: 63mW; TempCo: 100 ppm/C; Value_Code: 7k15; Value: 7.15k; EIA_Code: E96; SizeX_mm: 1; SizeY_mm: 0.5; SizeZ_mm: 0.6; Value2: 0.063W; AEC Qualified: Y; VDC_V: 50V; AEC Category: Q200; AEC Grade: 0
R337 R338 R343 R344 = CMP-0026938-5: RES, 4.7 k, 5%, 0.063 W, AEC-Q200 Grade 0, 0402; Manufacturer: Vishay-Dale; Power_W: 63mW; TempCo: 200 ppm/C; Value_Code: 4k70; Value: 4.7k; EIA_Code: E24; SizeX_mm: 1; SizeY_mm: 0.5; SizeZ_mm: 0.6; Value2: 0.063W; AEC Qualified: Y; VDC_V: 50V; AEC Category: Q200; AEC Grade: 0
R339 = CMP-0022599-4: RES, 7.15 k, 1%, 0.1 W, AEC-Q200 Grade 0, 0603; Manufacturer: Vishay-Dale; Power_W: 100mW; TempCo: 100 ppm/C; Value_Code: 7k15; Value: 7.15k; EIA_Code: E96; SizeX_mm: 1.6; SizeY_mm: 0.8; SizeZ_mm: 1; Value2: 0.1W; SizeArea_mm2: 1.28; AEC Qualified: Y; VDC_V: 75V; AEC Category: Q200; AEC Grade: 0
R342 R356 = CMP-0026021-3: RES, 150 k, 1%, 0.063 W, AEC-Q200 Grade 0, 0402; Manufacturer: Vishay-Dale; Power_W: 63mW; TempCo: 100 ppm/C; Value: 150k; EIA_Code: E96; SizeX_mm: 1; SizeY_mm: 0.5; SizeZ_mm: 0.6; Value2: 0.063W; AEC Qualified: Y; VDC_V: 50V; AEC Category: Q200; AEC Grade: 0
R345 R351 R353 = CMP-0016861-3: RES, 2.00 M, 1%, 0.25 W, AEC-Q200 Grade 0, 1206; Manufacturer: Vishay-Dale; Power_W: 250mW; TempCo: 100 ppm/C; Value_Code: 2M00; Value: 2.00Meg; EIA_Code: E96; Res_ohm: 2M; SizeX_mm: 3.2; SizeY_mm: 1.6; SizeZ_mm: 1.35; Value2: 0.25W; SizeArea_mm2: 5.12; AEC Qualified: Y; VDC_V: 200V; AEC Category: Q200; AEC Grade: 0
R346 R347 = CMP-0026070-3: RES, 19.6, 1%, 0.063 W, AEC-Q200 Grade 0, 0402; Manufacturer: Vishay-Dale; Power_W: 63mW; TempCo: 100 ppm/C; Value_Code: 19R6; Value: 19.6; EIA_Code: E96; SizeX_mm: 1; SizeY_mm: 0.5; SizeZ_mm: 0.6; Value2: 0.063W; AEC Qualified: Y; VDC_V: 50V; AEC Category: Q200; AEC Grade: 0
R350 R352 R355 = CMP-0016927-3: RES, 365 k, 1%, 0.25 W, AEC-Q200 Grade 0, 1206; Manufacturer: Vishay-Dale; Power_W: 250mW; TempCo: 100 ppm/C; Value: 365k; EIA_Code: E96; SizeX_mm: 3.2; SizeY_mm: 1.6; SizeZ_mm: 1.35; Value2: 0.25W; SizeArea_mm2: 5.12; AEC Qualified: Y; VDC_V: 200V; AEC Category: Q200; AEC Grade: 0
R357 R358 = CMP-0026328-2: RES, 39.2, 1%, 0.063 W, AEC-Q200 Grade 0, 0402; Manufacturer: Vishay-Dale; Power_W: 63mW; TempCo: 100 ppm/C; Value_Code: 39R2; Value: 39.2; EIA_Code: E96; SizeX_mm: 1; SizeY_mm: 0.5; SizeZ_mm: 0.6; Value2: 0.063W; AEC Qualified: Y; VDC_V: 50V; AEC Category: Q200; AEC Grade: 0
R359 R362 = CMP-0025814-4: RES, 47 k, 5%, 0.1 W, AEC-Q200 Grade 0, 0603; Manufacturer: Vishay-Dale; Power_W: 100mW; TempCo: 200 ppm/C; Value_Code: 47k0; Value: 47k; EIA_Code: E24; SizeX_mm: 1.6; SizeY_mm: 0.8; SizeZ_mm: 1; Value2: 0.1W; SizeArea_mm2: 1.28; AEC Qualified: Y; VDC_V: 75V; AEC Category: Q200; AEC Grade: 0
U301 U302 = CMP-0032028-2: CMOS Amplifier 1 Circuit Rail-to-Rail SOT-23-5; Manufacturer: Texas Instruments; SizeZ_mm: 1.45mm; AEC Qualified: No; Gain Bandwidth: 50MHz; Input Bias Current: 0.000005uA; Input Offset Voltage: 0.4mV; Max Supply Voltage: 5.5V; Min Supply Voltage: 2.2V; Nominal Supply Current: 4.6mA; Number Of Channels: 1; Output Current Per Channel: 85mA; Response Time: 0.2us; Standoff Height: 0mm; TaMax_C: +125°C; TaMin_C: -40°C; TJmax_C: +150°C; Voltage Gain: 120dB; AEC Category: Q200; CompType: IC
U303 U304 U306 = CMP-0077859-1: Automotive Qualified Precision, Zero-Crossover, 20MHz, 0.9pA Ib, RRIO, CMOS Operational Amplifier, DBV0005A (SOT-23-5); Alternate PartNumber: OPA320AQDBVTQ1; Alternate Manufacturer: Texas Instruments; SizeAreaWB_mm2: 14.82; SizeZ_mm: 1.45; SizeX_mm: 2.8; SizeY_mm: 2.9; SizeArea_mm2: 8.12; CompType: IC; AEC Qualified: Y; AEC Category: Q200
U305 = CMP-0068826-2: 17 MHz, Low Noise, CMOS Input, 1.8V Operational Amplifiers, DBV0005A (SOT-23-5); Manufacturer: Texas Instruments; CompType: IC; AEC Category: Q200; AEC Qualified: Y; Rating: Automotive; SizeAreaWB_mm2: 14.82; SizeArea_mm2: 8.12; SizeX_mm: 2.8; SizeY_mm: 2.9; SizeZ_mm: 1.45
U307 = CMP-0090884-2: ±50-mV input, precision reinforced isolated amplifier with integrated DC/DC converter 16-SOIC -40 to 125; Manufacturer: Texas Instruments; Max Supply Voltage: 5.5V; TaMax_C: +125°C; AEC Qualified: No; SizeZ_mm: 2.65mm; Input Bias Current: -36uA; Number Of Channels: 1; Nominal Supply Current: 27.5-29.5mA; Min Supply Voltage: 3V; Standoff Height: 0.1mm; TaMin_C: -40°C; TJmax_C: +150°C; Response Time: 0.9ms; Input Offset Voltage: 0.1mV; Output Current Per Channel: 14mA; AEC Category: Q200; CompType: IC
U308 = CMP-0090627-1: Precision, ±1-V Input, Reinforced Isolated Amplifier With Integrated DC/DC Converter; Manufacturer: Texas Instruments; Bandwidth: 310kHz; Max Supply Voltage: 5.5V; SizeZ_mm: 2.65mm; TaMax_C: +125°C; Min Supply Voltage: 3V; TaMin_C: -40°C; TJmax_C: +150°C; Nominal Supply Current: 27.5-28.5mA; AEC Grade: Grade 1; AEC Qualified: Yes; Number Of Channels: 1; Standoff Height: 0.1mm; Input Bias Current: 0.01uA

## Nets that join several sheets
5V_PRI: PMP23461 CLLLC Power Stage (6 pins), PMP23461 CLLLC Sensing (J309.7 J309.9 J313.5)
12V_PRI: PMP23461 CLLLC Power Stage (J300.9 J301.9 J302.9 J303.9), PMP23461 CLLLC Sensing (J309.2 J309.4)
DCLINK: PMP23461 CLLLC Power Stage (17 pins), PMP23461 CLLLC Sensing (R355.1)
PGND: PMP23461 CLLLC Power Stage (42 pins), PMP23461 CLLLC Sensing (46 pins)
SGND: PMP23461 CLLLC Power Stage (24 pins), PMP23461 CLLLC Sensing (FB300.1 FB301.1 R332.1 R333.2)
VBATT_F: PMP23461 CLLLC Power Stage (18 pins), PMP23461 CLLLC Sensing (R353.2)
BATT_RTN: PMP23461 CLLLC Power Stage (7 pins), PMP23461 CLLLC Sensing (FB302.1)
CLLLC_GAN_OC_PRIM_LEG1_H: PMP23461 CLLLC Power Stage (J302.4), PMP23461 CLLLC Sensing (J309.20)
CLLLC_GAN_OC_PRIM_LEG1_L: PMP23461 CLLLC Power Stage (J302.5), PMP23461 CLLLC Sensing (J309.18)
CLLLC_GAN_OC_PRIM_LEG2_H: PMP23461 CLLLC Power Stage (J300.4), PMP23461 CLLLC Sensing (J309.16)
CLLLC_GAN_OC_PRIM_LEG2_L: PMP23461 CLLLC Power Stage (J300.5), PMP23461 CLLLC Sensing (J309.19)
CLLLC_GAN_OC_SEC_LEG1_H: PMP23461 CLLLC Power Stage (J303.4), PMP23461 CLLLC Sensing (J309.17)
CLLLC_GAN_OC_SEC_LEG1_L: PMP23461 CLLLC Power Stage (J303.5), PMP23461 CLLLC Sensing (J309.15)
CLLLC_GAN_OC_SEC_LEG2_H: PMP23461 CLLLC Power Stage (J301.4), PMP23461 CLLLC Sensing (J309.13)
CLLLC_GAN_OC_SEC_LEG2_L: PMP23461 CLLLC Power Stage (J301.5), PMP23461 CLLLC Sensing (J309.11)
CLLLC_PRIM_FAULT_LEG1_H: PMP23461 CLLLC Power Stage (J302.6), PMP23461 CLLLC Sensing (J311.1)
CLLLC_PRIM_FAULT_LEG1_L: PMP23461 CLLLC Power Stage (J302.3), PMP23461 CLLLC Sensing (J311.3)
CLLLC_PRIM_FAULT_LEG2_H: PMP23461 CLLLC Power Stage (J300.6), PMP23461 CLLLC Sensing (J311.5)
CLLLC_PRIM_FAULT_LEG2_L: PMP23461 CLLLC Power Stage (J300.3), PMP23461 CLLLC Sensing (J311.7)
CLLLC_PRIM_LEG1_H: PMP23461 CLLLC Power Stage (J302.8), PMP23461 CLLLC Sensing (J313.12)
CLLLC_PRIM_LEG1_H_TEMP: PMP23461 CLLLC Power Stage (J302.2), PMP23461 CLLLC Sensing (J311.2)
CLLLC_PRIM_LEG1_L: PMP23461 CLLLC Power Stage (J302.1), PMP23461 CLLLC Sensing (J313.10)
CLLLC_PRIM_LEG1_L_TEMP: PMP23461 CLLLC Power Stage (J302.7), PMP23461 CLLLC Sensing (J311.10)
CLLLC_PRIM_LEG2_H: PMP23461 CLLLC Power Stage (J300.8), PMP23461 CLLLC Sensing (J313.8)
CLLLC_PRIM_LEG2_H_TEMP: PMP23461 CLLLC Power Stage (J300.2), PMP23461 CLLLC Sensing (J311.12)
CLLLC_PRIM_LEG2_L: PMP23461 CLLLC Power Stage (J300.1), PMP23461 CLLLC Sensing (J313.6)
CLLLC_PRIM_LEG2_L_TEMP: PMP23461 CLLLC Power Stage (J300.7), PMP23461 CLLLC Sensing (J311.4)
CLLLC_SEC_FAULT_LEG1_H: PMP23461 CLLLC Power Stage (J303.6), PMP23461 CLLLC Sensing (J311.11)
CLLLC_SEC_FAULT_LEG1_L: PMP23461 CLLLC Power Stage (J303.3), PMP23461 CLLLC Sensing (J311.9)
CLLLC_SEC_FAULT_LEG2_H: PMP23461 CLLLC Power Stage (J301.6), PMP23461 CLLLC Sensing (J311.13)
CLLLC_SEC_FAULT_LEG2_L: PMP23461 CLLLC Power Stage (J301.3), PMP23461 CLLLC Sensing (J311.15)
CLLLC_SEC_LEG1_H: PMP23461 CLLLC Power Stage (J303.8), PMP23461 CLLLC Sensing (J313.15)
CLLLC_SEC_LEG1_H_TEMP: PMP23461 CLLLC Power Stage (J303.2), PMP23461 CLLLC Sensing (J311.6)
CLLLC_SEC_LEG1_L: PMP23461 CLLLC Power Stage (J303.1), PMP23461 CLLLC Sensing (J313.13)
CLLLC_SEC_LEG1_L_TEMP: PMP23461 CLLLC Power Stage (J303.7), PMP23461 CLLLC Sensing (J311.14)
CLLLC_SEC_LEG2_H: PMP23461 CLLLC Power Stage (J301.8), PMP23461 CLLLC Sensing (J313.11)
CLLLC_SEC_LEG2_H_TEMP: PMP23461 CLLLC Power Stage (J301.2), PMP23461 CLLLC Sensing (J311.16)
CLLLC_SEC_LEG2_L: PMP23461 CLLLC Power Stage (J301.1), PMP23461 CLLLC Sensing (J313.9)
CLLLC_SEC_LEG2_L_TEMP: PMP23461 CLLLC Power Stage (J301.7), PMP23461 CLLLC Sensing (J311.8)
IPRI_SENSE: PMP23461 CLLLC Power Stage (6 pins), PMP23461 CLLLC Sensing (R348.2)
ROG_PRI_N: PMP23461 CLLLC Power Stage (T300.2), PMP23461 CLLLC Sensing (R322.1)
ROG_PRI_P: PMP23461 CLLLC Power Stage (T300.1), PMP23461 CLLLC Sensing (R327.1)
ROG_SEC_N: PMP23461 CLLLC Power Stage (J304.2), PMP23461 CLLLC Sensing (R312.1)
ROG_SEC_P: PMP23461 CLLLC Power Stage (J304.1), PMP23461 CLLLC Sensing (R314.1)
SYSTEM_TEMP_1: PMP23461 CLLLC Power Stage (C318.1 R307.2), PMP23461 CLLLC Sensing (J313.19)

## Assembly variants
001: not fitted C331 C332 C334 C336 C340 C341 C342 C343 C345 C347 C351 R310 R335 R349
